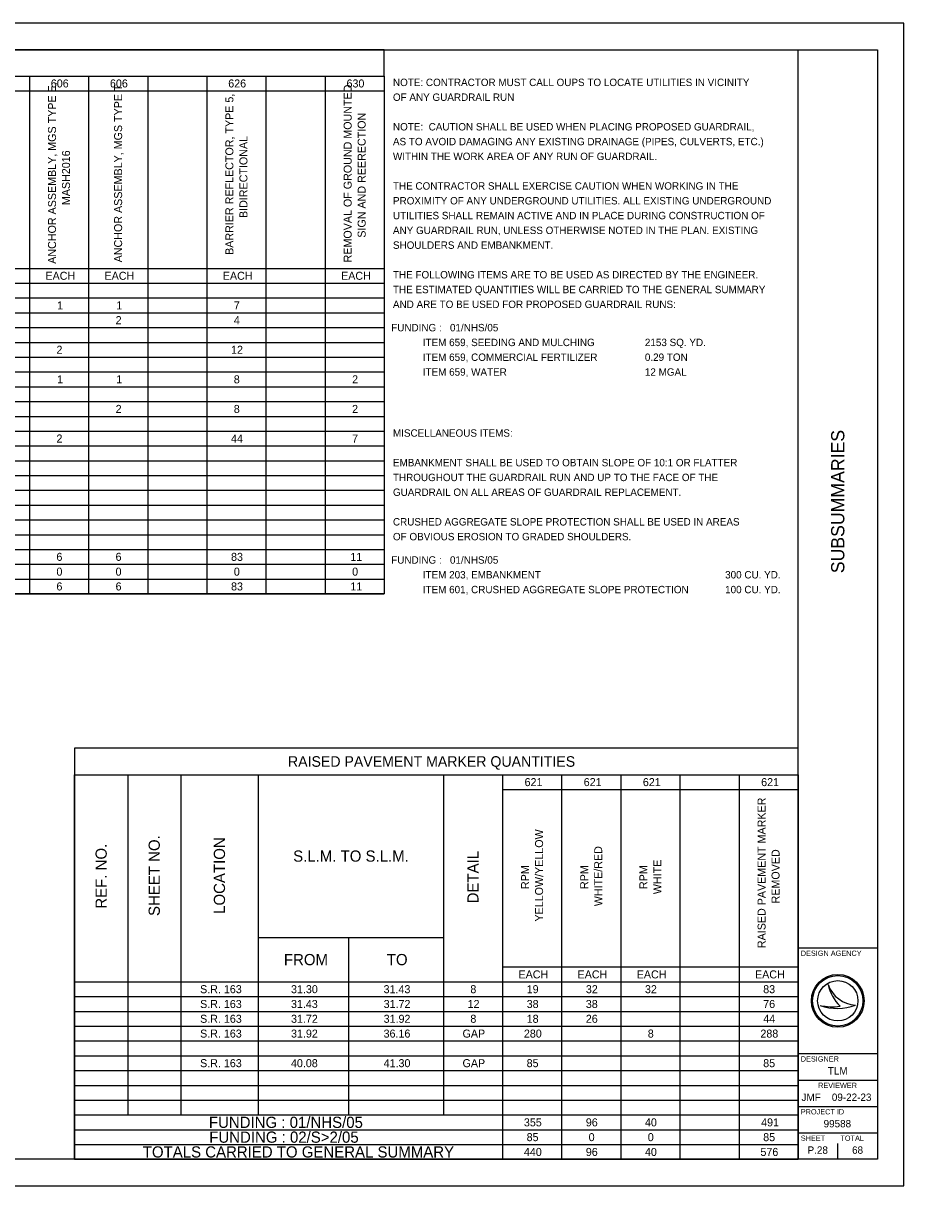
# Model space of a CAD drawing. Extents: x 0 to 34, y 0 to 22.
# Drawn here: x 17.32 to 34, y 0 to 22 of the extents above; entities that cross this region are included whole.
import ezdxf

# ---------------------------------------------------------------- set-up
doc = ezdxf.new("R2010")
doc.units = 0
for name, color, linetype in [('Default', 7, 'Continuous'), ('SH_Border', 7, 'Continuous'), ('SH_Cut_Line', 7, 'Continuous'), ('SH_Data', 7, 'Continuous'), ('SH_Text', 7, 'Continuous')]:
    doc.layers.add(name, color=color, linetype=linetype)

msp = doc.modelspace()

# ---------------------------------------------------------------- linework, layer by layer
at = {"layer": 'Default'}
for p, q in [((1.5, 21), (24.161, 21)), ((17.442, 21), (17.442, 11.202)), ((18.562, 21), (18.562, 11.202)), ((19.681, 21), (19.681, 11.202)), ((20.801, 21), (20.801, 11.202)), ((21.921, 21), (21.921, 11.202)), ((23.041, 21), (23.041, 11.202)), ((24.161, 21), (24.161, 11.202)), ((8.483, 20.72), (24.161, 20.72)), ((8.483, 17.361), (24.161, 17.361)), ((1.5, 17.081), (24.161, 17.081)), ((1.5, 16.801), (24.161, 16.801)), ((1.5, 16.521), (24.161, 16.521)), ((1.5, 16.241), (24.161, 16.241)), ((1.5, 15.961), (24.161, 15.961)), ((1.5, 15.681), (24.161, 15.681)), ((1.5, 15.401), (24.161, 15.401)), ((1.5, 15.121), (24.161, 15.121)), ((1.5, 14.841), (24.161, 14.841)), ((1.5, 14.561), (24.161, 14.561)), ((1.5, 14.281), (24.161, 14.281)), ((1.5, 14.001), (24.161, 14.001)), ((1.5, 13.721), (24.161, 13.721)), ((1.5, 13.441), (24.161, 13.441)), ((1.5, 13.161), (24.161, 13.161)), ((1.5, 12.881), (24.161, 12.881)), ((1.5, 12.601), (24.161, 12.601)), ((1.5, 12.321), (24.161, 12.321)), ((1.5, 12.041), (24.161, 12.041)), ((1.5, 11.761), (24.161, 11.761)), ((1.5, 11.482), (24.161, 11.482)), ((1.5, 11.202), (24.161, 11.202))]:
    msp.add_line(p, q, dxfattribs=at)
at = {"layer": 'SH_Border'}
for p, q in [((32, 0.5), (32, 21.5)), ((32, 4.5), (33.5, 4.5)), ((32, 2.5), (33.5, 2.5)), ((32, 2), (33.5, 2)), ((32, 1.5), (33.5, 1.5)), ((32, 1), (33.5, 1))]:
    msp.add_line(p, q, dxfattribs=at)
msp.add_lwpolyline([(1.5, 21.5), (33.5, 21.5), (33.5, 0.5), (1.5, 0.5)], close=True, dxfattribs=at)
at = {"layer": 'SH_Cut_Line'}
msp.add_lwpolyline([(0, 0), (34, 0), (34, 22), (0, 22)], close=True, dxfattribs=at)
at = {"layer": 'SH_Data'}
for p, q in [((32.567, 3.81), (32.567, 3.81)), ((32.417, 3.41), (32.417, 3.41)), ((32.75, 3.5), (32.75, 3.5)), ((33.087, 3.419), (33.087, 3.419)), ((32.375, 0.675), (32.375, 0.675)), ((32.75, 0.5), (32.75, 0.8))]:
    msp.add_line(p, q, dxfattribs=at)
for radius in [0.5, 0.477, 0.477, 0.382]:
    msp.add_circle((32.75, 3.5), radius, dxfattribs=at)
for centre, radius, start, end in [((33.116, 3.998), 0.58, 198.9257, 198.9319), ((33.347, 3.97), 0.796, 191.6379, 191.6421), ((33.116, 3.998), 0.58, 198.9319, 267.1657), ((33.347, 3.97), 0.796, 191.6421, 226.0947), ((32.739, 4.37), 1.013, 251.4576, 290.0832), ((32.648, 4.654), 1.266, 259.4964, 259.4995), ((32.739, 4.37), 1.013, 251.4527, 251.4576), ((32.648, 4.654), 1.266, 259.4995, 276.6672)]:
    msp.add_arc(centre, radius, start, end, dxfattribs=at)
at = {"layer": 'SH_Text'}
for p, q in [((18.298, 7.779), (32, 7.779)), ((18.298, 7.779), (18.298, 0.5)), ((19.303, 7.779), (19.303, 1.34)), ((20.307, 7.779), (20.307, 1.34)), ((21.773, 7.779), (21.773, 1.34)), ((25.281, 7.779), (25.281, 1.34)), ((26.401, 7.779), (26.401, 0.5)), ((27.521, 7.779), (27.521, 0.5)), ((28.64, 7.779), (28.64, 0.5)), ((29.76, 7.779), (29.76, 0.5)), ((30.88, 7.779), (30.88, 0.5)), ((32, 7.779), (32, 0.5)), ((26.401, 7.499), (32, 7.499)), ((21.773, 4.7), (25.281, 4.7)), ((23.486, 4.7), (23.486, 1.34)), ((26.401, 4.14), (32, 4.14)), ((18.298, 3.86), (32, 3.86)), ((18.298, 3.58), (32, 3.58)), ((18.298, 3.3), (32, 3.3)), ((18.298, 3.02), (32, 3.02)), ((18.298, 2.74), (32, 2.74)), ((18.298, 2.46), (32, 2.46)), ((18.298, 2.18), (32, 2.18)), ((18.298, 1.9), (32, 1.9)), ((18.298, 1.62), (32, 1.62)), ((18.298, 1.34), (32, 1.34)), ((18.298, 1.06), (32, 1.06)), ((18.298, 0.78), (32, 0.78)), ((18.298, 0.5), (32, 0.5))]:
    msp.add_line(p, q, dxfattribs=at)
for points in [[(1.5, 21), (24.161, 21), (24.161, 21.5), (1.5, 21.5)], [(1.5, 21), (24.161, 21), (24.161, 11.202), (1.5, 11.202)], [(18.298, 7.779), (32, 7.779), (32, 8.279), (18.298, 8.279)], [(18.298, 7.779), (32, 7.779), (32, 0.5), (18.298, 0.5)]]:
    msp.add_lwpolyline(points, close=True, dxfattribs=at)

# ---------------------------------------------------------------- texts
at = {"layer": 'Default'}
for s, height, p in [('606', 0.1515, (17.847, 20.785)), ('606', 0.1515, (18.967, 20.785)), ('626', 0.1515, (21.207, 20.785)), ('630', 0.1515, (23.447, 20.785)), ('NOTE: CONTRACTOR MUST CALL OUPS TO LOCATE UTILITIES IN VICINITY ', 0.14, (24.326, 20.811)), ('OF ANY GUARDRAIL RUN', 0.14, (24.326, 20.531)), ('NOTE:  CAUTION SHALL BE USED WHEN PLACING PROPOSED GUARDRAIL,', 0.14, (24.326, 19.971)), ('AS TO AVOID DAMAGING ANY EXISTING DRAINAGE (PIPES, CULVERTS, ETC.)', 0.14, (24.326, 19.691)), ('WITHIN THE WORK AREA OF ANY RUN OF GUARDRAIL.', 0.14, (24.326, 19.411)), ('THE CONTRACTOR SHALL EXERCISE CAUTION WHEN WORKING IN THE', 0.14, (24.326, 18.851)), ('PROXIMITY OF ANY UNDERGROUND UTILITIES. ALL EXISTING UNDERGROUND', 0.14, (24.326, 18.571)), ('UTILITIES SHALL REMAIN ACTIVE AND IN PLACE DURING CONSTRUCTION OF', 0.14, (24.326, 18.291)), ('ANY GUARDRAIL RUN, UNLESS OTHERWISE NOTED IN THE PLAN. EXISTING', 0.14, (24.326, 18.011)), ('SHOULDERS AND EMBANKMENT.', 0.14, (24.326, 17.731)), ('EACH', 0.1515, (17.745, 17.145)), ('EACH', 0.1515, (18.864, 17.145)), ('EACH', 0.1515, (21.104, 17.145)), ('EACH', 0.1515, (23.344, 17.145)), ('THE FOLLOWING ITEMS ARE TO BE USED AS DIRECTED BY THE ENGINEER.', 0.14, (24.326, 17.171)), ('THE ESTIMATED QUANTITIES WILL BE CARRIED TO THE GENERAL SUMMARY', 0.14, (24.326, 16.891)), ('1', 0.152, (17.966, 16.585)), ('1', 0.152, (19.086, 16.585)), ('7', 0.152, (21.313, 16.585)), ('AND ARE TO BE USED FOR PROPOSED GUARDRAIL RUNS:', 0.14, (24.326, 16.611)), ('2', 0.152, (19.074, 16.305)), ('4', 0.152, (21.313, 16.305)), ('FUNDING :   01/NHS/05', 0.14, (24.293, 16.17)), ('2', 0.152, (17.954, 15.745)), ('12', 0.1515, (21.26, 15.745)), ('ITEM 659, SEEDING AND MULCHING', 0.14, (24.891, 15.89)), ('2153 SQ. YD.', 0.14, (29.097, 15.89)), ('ITEM 659, COMMERCIAL FERTILIZER', 0.14, (24.891, 15.61)), ('0.29 TON', 0.14, (29.097, 15.61)), ('ITEM 659, WATER', 0.14, (24.891, 15.33)), ('12 MGAL', 0.14, (29.097, 15.33)), ('1', 0.152, (17.966, 15.185)), ('1', 0.152, (19.086, 15.185)), ('8', 0.152, (21.312, 15.185)), ('2', 0.152, (23.553, 15.185)), ('2', 0.152, (19.074, 14.625)), ('8', 0.152, (21.312, 14.625)), ('2', 0.152, (23.553, 14.625)), ('MISCELLANEOUS ITEMS:', 0.14, (24.326, 14.175)), ('2', 0.152, (17.954, 14.065)), ('44', 0.1515, (21.26, 14.065)), ('7', 0.152, (23.552, 14.065)), ('EMBANKMENT SHALL BE USED TO OBTAIN SLOPE OF 10:1 OR FLATTER', 0.14, (24.326, 13.615)), ('THROUGHOUT THE GUARDRAIL RUN AND UP TO THE FACE OF THE', 0.14, (24.326, 13.335)), ('GUARDRAIL ON ALL AREAS OF GUARDRAIL REPLACEMENT.', 0.14, (24.326, 13.055)), ('CRUSHED AGGREGATE SLOPE PROTECTION SHALL BE USED IN AREAS', 0.14, (24.326, 12.495)), ('OF OBVIOUS EROSION TO GRADED SHOULDERS.', 0.14, (24.326, 12.215)), ('6', 0.152, (17.953, 11.826)), ('6', 0.152, (19.073, 11.826)), ('83', 0.1515, (21.26, 11.826)), ('11', 0.1515, (23.52, 11.826)), ('FUNDING :   01/NHS/05', 0.14, (24.293, 11.773)), ('0', 0.152, (17.953, 11.546)), ('0', 0.152, (19.073, 11.546)), ('0', 0.152, (21.313, 11.546)), ('0', 0.152, (23.553, 11.546)), ('ITEM 203, EMBANKMENT', 0.14, (24.891, 11.493)), ('300 CU. YD.', 0.14, (30.617, 11.493)), ('6', 0.152, (17.953, 11.266)), ('6', 0.152, (19.073, 11.266)), ('83', 0.1515, (21.26, 11.266)), ('11', 0.1515, (23.52, 11.266)), ('ITEM 601, CRUSHED AGGREGATE SLOPE PROTECTION', 0.14, (24.891, 11.213)), ('100 CU. YD.', 0.14, (30.617, 11.213))]:
    msp.add_text(s, height=height, dxfattribs=at).set_placement(p)
for s, height, p in [('ANCHOR ASSEMBLY, MGS TYPE E, ', 0.15151, (17.945, 17.448)), ('ANCHOR ASSEMBLY, MGS TYPE T', 0.15151, (19.197, 17.475)), ('REMOVAL OF GROUND MOUNTED ', 0.15151, (23.544, 17.474)), ('BARRIER REFLECTOR, TYPE 5, ', 0.15151, (21.304, 17.616)), ('SIGN AND REERECTION', 0.15151, (23.809, 17.942)), ('BIDIRECTIONAL', 0.15151, (21.57, 18.314)), ('MASH2016', 0.1515, (18.21, 18.558))]:
    msp.add_text(s, height=height, rotation=90, dxfattribs=at).set_placement(p)
at = {"layer": 'SH_Data'}
msp.add_text('SUBSUMMARIES', height=0.25, rotation=90, dxfattribs=at).set_placement((32.875, 11.592))
for s, height, p in [('DESIGN AGENCY', 0.1, (32.05, 4.35)), ('DESIGNER', 0.1, (32.05, 2.35)), ('TLM', 0.14, (32.562, 2.105)), ('REVIEWER', 0.1, (32.378, 1.85)), ('JMF', 0.14, (32.064, 1.605)), ('09-22-23', 0.14, (32.638, 1.605)), ('PROJECT ID', 0.1, (32.05, 1.35)), ('99588', 0.14, (32.482, 1.105)), ('SHEET', 0.1, (32.05, 0.85)), ('TOTAL', 0.1, (32.8, 0.85)), ('P.28', 0.14, (32.178, 0.605)), ('68', 0.14, (33.021, 0.605))]:
    msp.add_text(s, height=height, dxfattribs=at).set_placement(p)
at = {"layer": 'SH_Text'}
for s, height, p in [('RAISED PAVEMENT MARKER QUANTITIES', 0.2, (22.338, 7.929)), ('621', 0.1515, (26.819, 7.563)), ('621', 0.1515, (27.939, 7.563)), ('621', 0.1515, (29.059, 7.563)), ('621', 0.1515, (31.299, 7.563)), ('S.L.M. TO S.L.M.', 0.21212, (22.436, 6.133)), ('FROM', 0.2121, (22.261, 4.174)), ('TO', 0.2121, (24.21, 4.174)), ('EACH', 0.1515, (26.704, 3.924)), ('EACH', 0.1515, (27.823, 3.924)), ('EACH', 0.1515, (28.943, 3.924)), ('EACH', 0.1515, (31.183, 3.924)), ('S.R. 163', 0.1515, (20.674, 3.644)), ('31.30', 0.1515, (22.396, 3.644)), ('31.43', 0.1515, (24.149, 3.644)), ('8', 0.152, (25.792, 3.644)), ('19', 0.1515, (26.859, 3.644)), ('32', 0.1515, (27.98, 3.644)), ('32', 0.1515, (29.099, 3.644)), ('83', 0.1515, (31.338, 3.644)), ('S.R. 163', 0.1515, (20.674, 3.364)), ('31.43', 0.1515, (22.395, 3.364)), ('31.72', 0.1515, (24.15, 3.364)), ('12', 0.1515, (25.74, 3.364)), ('38', 0.1515, (26.859, 3.364)), ('38', 0.1515, (27.979, 3.364)), ('76', 0.1515, (31.338, 3.364)), ('S.R. 163', 0.1515, (20.674, 3.084)), ('31.72', 0.1515, (22.396, 3.084)), ('31.92', 0.1515, (24.15, 3.084)), ('8', 0.152, (25.792, 3.084)), ('18', 0.1515, (26.859, 3.084)), ('26', 0.1515, (27.979, 3.084)), ('44', 0.1515, (31.339, 3.084)), ('S.R. 163', 0.1515, (20.674, 2.804)), ('31.92', 0.1515, (22.396, 2.804)), ('36.16', 0.1515, (24.149, 2.804)), ('GAP', 0.1515, (25.644, 2.804)), ('280', 0.1515, (26.806, 2.804)), ('8', 0.152, (29.152, 2.804)), ('288', 0.1515, (31.285, 2.804)), ('S.R. 163', 0.1515, (20.674, 2.244)), ('40.08', 0.1515, (22.395, 2.244)), ('41.30', 0.1515, (24.15, 2.244)), ('GAP', 0.1515, (25.644, 2.244)), ('85', 0.1515, (26.858, 2.244)), ('85', 0.1515, (31.338, 2.244)), ('FUNDING : 01/NHS/05', 0.21212, (20.841, 1.094)), ('355', 0.1515, (26.806, 1.124)), ('96', 0.1515, (27.979, 1.124)), ('40', 0.1515, (29.099, 1.124)), ('491', 0.1515, (31.299, 1.124)), ('FUNDING : 02/S>2/05', 0.21212, (20.847, 0.814)), ('85', 0.1515, (26.858, 0.844)), ('0', 0.152, (28.032, 0.844)), ('0', 0.152, (29.152, 0.844)), ('85', 0.1515, (31.338, 0.844)), ('TOTALS CARRIED TO GENERAL SUMMARY', 0.21212, (19.589, 0.534)), ('440', 0.1515, (26.806, 0.564)), ('96', 0.1515, (27.979, 0.564)), ('40', 0.1515, (29.099, 0.564)), ('576', 0.1515, (31.286, 0.564))]:
    msp.add_text(s, height=height, dxfattribs=at).set_placement(p)
for s, height, p in [('RAISED PAVEMENT MARKER ', 0.15151, (31.383, 4.497)), ('SHEET NO.', 0.2121, (19.911, 5.105)), ('YELLOW/YELLOW', 0.15151, (27.169, 5)), ('REF. NO.', 0.2121, (18.906, 5.243)), ('LOCATION', 0.2121, (21.146, 5.145)), ('WHITE/RED', 0.1515, (28.289, 5.29)), ('DETAIL', 0.2121, (25.947, 5.344)), ('WHITE', 0.1515, (29.409, 5.518)), ('REMOVED', 0.1515, (31.648, 5.343)), ('RPM', 0.1515, (26.904, 5.615)), ('RPM', 0.1515, (28.024, 5.615)), ('RPM', 0.1515, (29.144, 5.615))]:
    msp.add_text(s, height=height, rotation=90, dxfattribs=at).set_placement(p)

doc.saveas('drawing.dxf')
